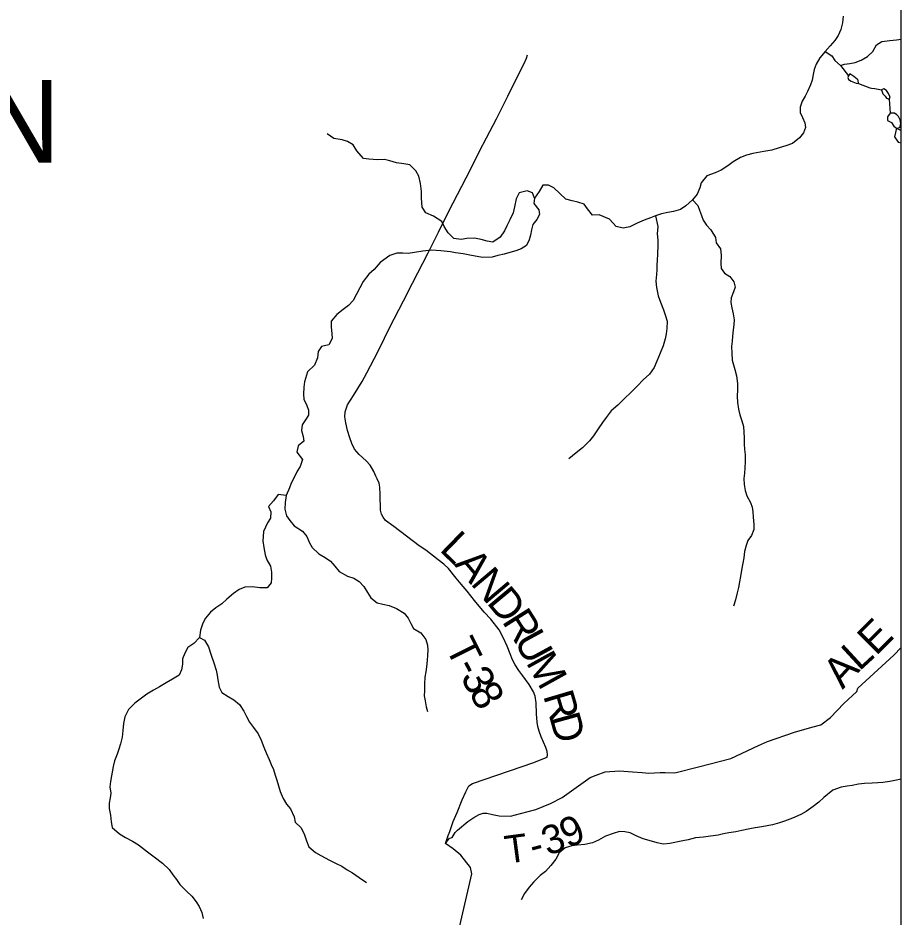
# Model space of a CAD drawing. Extents: x -139 to 835, y 0 to 440.
# Drawn here: x 550 to 607.6, y 239.4 to 298.1 of the extents above; entities that cross this region are included whole.
import ezdxf

# ---------------------------------------------------------------- set-up
doc = ezdxf.new("R2010")
doc.units = 0
for name, color, linetype in [('Default', 7, 'Continuous'), ('GM_X_Minor_Lake', 7, 'Continuous'), ('GM_X_Minor_River', 7, 'Continuous'), ('GM_X_Township_Road', 7, 'Continuous'), ('GM_X_Township_Road_Text', 7, 'Continuous'), ('GM_X_Township_Text', 7, 'Continuous'), ('SH_Cut_Line', 7, 'Continuous')]:
    doc.layers.add(name, color=color, linetype=linetype)

msp = doc.modelspace()

# ---------------------------------------------------------------- linework, layer by layer
at = {"layer": 'Default'}
msp.add_lwpolyline([(533.705, 218.461), (553.865, 217.083), (607.596, 213.413), (607.596, 313.688), (599.523, 343.435), (599.103, 345.232), (598.348, 346.669), (593.771, 354.537), (573.292, 389.29), (556.01, 382.105), (544.238, 377.806)], dxfattribs=at)
at = {"layer": 'GM_X_Minor_Lake'}
for points in [[(604.811, 294.022), (604.733, 294.095), (604.527, 294.265), (604.268, 294.424), (604.163, 294.305), (604.135, 294.186), (604.173, 294.065), (604.354, 293.955), (604.665, 293.82), (604.821, 293.794)], [(604.821, 293.794), (604.811, 294.022)], [(606.894, 292.884), (606.869, 292.957), (606.78, 293.15), (606.653, 293.343), (606.471, 293.453), (606.314, 293.395), (606.402, 293.118), (606.57, 292.984), (606.646, 292.839), (606.815, 292.777)], [(606.815, 292.777), (606.894, 292.884)], [(606.881, 291.877), (606.709, 291.639), (606.719, 291.387), (606.978, 291.264), (607.118, 291.023), (607.299, 290.889), (607.521, 290.922), (607.576, 291.162), (607.54, 291.426), (607.426, 291.643), (607.323, 291.764), (607.168, 291.862)], [(607.168, 291.862), (606.881, 291.877)]]:
    msp.add_lwpolyline(points, dxfattribs=at)
at = {"layer": 'GM_X_Minor_River'}
msp.add_line((607.299, 290.889), (607.596, 290.733), dxfattribs=at)
for points in [[(603.834, 298.184), (603.777, 297.764), (603.667, 297.322), (603.506, 296.928), (603.293, 296.606), (602.976, 296.262), (602.658, 295.893), (602.314, 295.465), (602.074, 295.072), (601.939, 294.713), (601.87, 294.39), (601.8, 294.019), (601.705, 293.708), (601.504, 293.278), (601.344, 292.968), (601.157, 292.658), (601.022, 292.264), (601.03, 291.904), (601.17, 291.59), (601.334, 291.241), (601.37, 290.928), (601.235, 290.594), (600.97, 290.249), (600.522, 289.894), (600.09, 289.731), (599.658, 289.603), (599.174, 289.452), (598.652, 289.362), (597.947, 289.238), (597.515, 289.134), (597.135, 288.983), (596.662, 288.688), (596.307, 288.428), (595.874, 288.156), (595.48, 287.969), (594.943, 287.77), (594.573, 287.319), (594.491, 287.008), (594.303, 286.59), (593.998, 286.221), (593.563, 285.818), (593.221, 285.594), (592.763, 285.455), (592.398, 285.399), (591.979, 285.295), (591.6, 285.167), (591.273, 285.051), (590.866, 284.887), (590.395, 284.688), (589.923, 284.466), (589.491, 284.374), (589.024, 284.475), (588.587, 284.948), (587.926, 285.231), (587.482, 285.212), (587.162, 285.623), (586.944, 285.925), (586.529, 286.074), (586.165, 286.15), (585.749, 286.262), (584.964, 287.002), (584.614, 287.162), (584.262, 287.166), (584.009, 286.749), (583.717, 286.32), (583.674, 285.973), (583.994, 285.561), (584.029, 285.249), (583.869, 284.939), (583.591, 284.606), (583.508, 284.259), (583.439, 283.912), (583.37, 283.601), (583.195, 283.231), (582.841, 283.031), (582.487, 282.89), (582.108, 282.787), (581.742, 282.682), (581.31, 282.579), (580.944, 282.475), (580.318, 282.446), (579.486, 282.599), (579.057, 282.688), (578.563, 282.765), (578.225, 282.816), (577.6, 282.895), (576.988, 282.926), (576.427, 282.86), (575.892, 282.782), (575.474, 282.714)], [(603.663, 294.983), (603.912, 295.052), (604.251, 295.108), (604.617, 295.176), (604.997, 295.328), (605.417, 295.563), (605.76, 295.884), (606, 296.313), (606.342, 296.549), (606.877, 296.604), (607.308, 296.659), (607.596, 296.702)], [(602.658, 295.893), (603.098, 295.612), (603.289, 295.31), (603.663, 294.983), (604.163, 294.305)], [(604.821, 293.794), (605.571, 293.525), (605.668, 293.49), (605.899, 293.472), (606.314, 293.395)], [(606.815, 292.777), (606.881, 291.877)], [(607.299, 290.889), (607.174, 290.326), (607.404, 289.976), (607.596, 289.933)], [(583.717, 286.32), (583.578, 286.681), (583.228, 286.805), (582.718, 286.667), (582.518, 286.285), (582.407, 285.77), (582.31, 285.364), (582.109, 284.922), (581.909, 284.516), (581.748, 284.194), (581.469, 283.777), (580.996, 283.446), (580.632, 283.51), (580.229, 283.623), (579.787, 283.711), (579.305, 283.693), (578.939, 283.625), (578.457, 283.69), (578.071, 284.066), (577.829, 284.476), (577.664, 284.802), (577.134, 285.156), (576.615, 285.365), (576.385, 285.728), (576.363, 286.028), (576.341, 286.34), (576.333, 286.76), (576.288, 287.276), (576.177, 287.769), (575.973, 288.107), (575.587, 288.495), (575.184, 288.572), (574.716, 288.637), (574.274, 288.761), (573.936, 288.849), (573.48, 288.83), (572.92, 288.86), (572.569, 288.912), (572.119, 289.409), (571.889, 289.795), (571.514, 290.027), (571.177, 290.127), (570.631, 290.217), (570.204, 290.509)], [(593.998, 286.221), (594.358, 285.857), (594.459, 285.544), (594.585, 285.195), (594.711, 284.882), (594.915, 284.568), (595.198, 284.253), (595.504, 283.758), (595.552, 283.421), (595.834, 283.022), (595.881, 282.614), (595.848, 282.063), (595.87, 281.738), (596.1, 281.436), (596.436, 281.216), (596.706, 280.866), (596.792, 280.529), (596.684, 280.206), (596.523, 279.836), (596.506, 279.512), (596.566, 279.164), (596.653, 278.779), (596.713, 278.382), (596.709, 278.071), (596.665, 277.735), (596.608, 277.316), (596.591, 277.004), (596.547, 276.657), (596.568, 276.225), (596.601, 275.757), (596.675, 275.456), (596.763, 275.143), (596.875, 274.734), (596.947, 274.241), (596.941, 273.833), (596.91, 273.414), (596.931, 272.994), (597.003, 272.573), (597.09, 272.2), (597.228, 271.815), (597.328, 271.442), (597.362, 271.07), (597.37, 270.686), (597.378, 270.29), (597.4, 269.942), (597.434, 269.582), (597.442, 269.126), (597.423, 268.73), (597.393, 268.395), (597.362, 268.035), (597.384, 267.663), (597.431, 267.267), (597.543, 266.905), (597.786, 266.483), (597.886, 266.17), (597.934, 265.87), (597.956, 265.522), (598.002, 265.053), (598.011, 264.717), (597.862, 264.323), (597.611, 264.002), (597.502, 263.667), (597.406, 263.284), (597.349, 262.877), (597.292, 262.518), (597.208, 262.075), (597.125, 261.656), (597.068, 261.309), (596.998, 260.926), (596.928, 260.578), (596.805, 260.124), (596.683, 259.729)], [(591.6, 285.167), (591.747, 284.482), (591.702, 284.003), (591.736, 283.582), (591.745, 283.258), (591.724, 282.683), (591.706, 282.287), (591.689, 281.963), (591.672, 281.652), (591.655, 281.352), (591.623, 280.908), (591.657, 280.5), (591.768, 279.947), (591.919, 279.538), (592.108, 279.032), (592.234, 278.719), (592.346, 278.297), (592.34, 277.818), (592.296, 277.482), (592.227, 277.147), (592.091, 276.693), (591.902, 276.227), (591.687, 275.701), (591.512, 275.283), (591.194, 274.843), (590.798, 274.475), (590.415, 274.084), (589.98, 273.656), (589.571, 273.265), (589.135, 272.826), (588.713, 272.447), (588.369, 272.03), (588.13, 271.697), (587.864, 271.28), (587.546, 270.828), (587.294, 270.507), (586.832, 270.044), (586.424, 269.712), (585.95, 269.333)], [(575.474, 282.714), (575.135, 282.73), (574.744, 282.734), (574.286, 282.583), (573.655, 282.122), (573.258, 281.683), (572.902, 281.362), (572.544, 280.887), (572.317, 280.481), (572.117, 280.063), (571.89, 279.646), (571.586, 279.325), (571.231, 279.065), (570.823, 278.746), (570.452, 278.306), (570.447, 277.922), (570.507, 277.502), (570.529, 277.177), (570.302, 276.76), (569.831, 276.645), (569.619, 276.336), (569.574, 275.904), (569.36, 275.427), (568.924, 275), (568.72, 274.354), (568.677, 273.995), (568.645, 273.551), (568.68, 273.227), (568.87, 272.805), (568.97, 272.504), (568.979, 272.18), (568.78, 271.87), (568.567, 271.537), (568.523, 271.177), (568.636, 270.792), (568.671, 270.48), (568.315, 270.172), (568.218, 269.753), (568.577, 269.281), (568.428, 268.827), (568.229, 268.517), (568.014, 268.064), (567.854, 267.742), (567.732, 267.431), (567.518, 266.941), (567.447, 266.486), (567.441, 266.043), (567.553, 265.609), (567.757, 265.295), (568.04, 264.968), (568.583, 264.615), (568.865, 264.264), (569.042, 263.854), (569.208, 263.552), (569.659, 263.14), (570.059, 262.883), (570.421, 262.651), (570.704, 262.337), (570.986, 261.986), (571.53, 261.68), (571.932, 261.543), (572.281, 261.336), (572.59, 261.009), (572.819, 260.61), (573.036, 260.272), (573.462, 259.944), (573.826, 259.844), (574.229, 259.767), (574.721, 259.57), (575.213, 259.265), (575.482, 258.938), (575.647, 258.588), (575.826, 258.263), (576.291, 257.97), (576.624, 257.546), (576.724, 257.173), (576.759, 256.849), (576.729, 256.514), (576.711, 256.166), (576.667, 255.771), (576.624, 255.447), (576.567, 255.088), (576.548, 254.644), (576.53, 254.225), (576.525, 253.877), (576.573, 253.552), (576.647, 253.156), (576.734, 252.843)], [(567.518, 266.941), (567.01, 266.995), (566.692, 266.578), (566.375, 266.222), (566.527, 265.872), (566.508, 265.453), (566.309, 265.143), (566.054, 264.594), (566.024, 264.27), (566.007, 263.971), (566.067, 263.538), (566.165, 263.057), (566.265, 262.732), (566.507, 262.334), (566.568, 261.937), (566.562, 261.542), (566.546, 261.242), (566.281, 260.909), (565.799, 260.914), (565.33, 260.979), (564.822, 260.949), (564.455, 260.809), (564.1, 260.549), (563.652, 260.17), (563.322, 259.861), (562.941, 259.601), (562.585, 259.329), (562.268, 258.937), (562.081, 258.615), (561.945, 258.149), (561.874, 257.67), (561.504, 257.29), (561.122, 257.018), (560.909, 256.649), (560.774, 256.29), (560.757, 255.93), (560.7, 255.571), (560.552, 255.225), (560.106, 254.954), (559.699, 254.718), (559.265, 254.459), (558.884, 254.235), (558.451, 253.988), (558.004, 253.657), (557.649, 253.385), (557.252, 252.97), (556.999, 252.492), (556.915, 252.062), (556.883, 251.618), (556.825, 251.175), (556.729, 250.732), (556.607, 250.386), (556.499, 250.063), (556.337, 249.633), (556.241, 249.274), (556.072, 248.292), (556.028, 247.933), (556.088, 247.524), (556.045, 247.213), (555.976, 246.878), (555.984, 246.53), (556.083, 246.097), (556.117, 245.665), (556.19, 245.28), (556.667, 244.867), (557.055, 244.635), (557.508, 244.402), (557.909, 244.146), (558.49, 243.708), (558.929, 243.379), (559.471, 242.954), (559.908, 242.541), (560.126, 242.203), (560.369, 241.888), (560.6, 241.574), (561.037, 241.138), (561.372, 240.798), (561.667, 240.447), (561.859, 240.133), (562.036, 239.735), (562.109, 239.351)], [(561.874, 257.67), (562.197, 257.498), (562.465, 257.076), (562.641, 256.534), (562.817, 256.028), (562.954, 255.535), (563.028, 255.222), (563.076, 254.91), (563.149, 254.429), (563.34, 254.091), (563.753, 253.823), (564.115, 253.615), (564.476, 253.311), (564.757, 252.864), (564.936, 252.527), (565.127, 252.165), (565.396, 251.814), (565.703, 251.403), (565.893, 250.981), (566.07, 250.535), (566.209, 250.15), (566.412, 249.728), (566.551, 249.39), (566.69, 249.077), (566.815, 248.692), (566.916, 248.367), (567.028, 248.006), (567.141, 247.633), (567.331, 247.187), (567.547, 246.813), (567.804, 246.498), (568.045, 245.992), (568.119, 245.643), (568.505, 245.255), (568.721, 244.797), (568.846, 244.424), (569.011, 244.026), (569.436, 243.662), (569.772, 243.466), (570.355, 243.148), (570.782, 242.939), (571.158, 242.755), (571.494, 242.536), (571.843, 242.34), (572.282, 242.024), (572.76, 241.707)], [(607.596, 248.431), (607.198, 248.353), (606.871, 248.296), (606.414, 248.229), (606.075, 248.209), (605.71, 248.177), (605.214, 248.146), (604.823, 248.115), (604.405, 248.035), (604.079, 247.979), (603.7, 247.911), (603.163, 247.725), (602.571, 247.251), (602.241, 246.931), (601.872, 246.659), (601.412, 246.328), (601.057, 246.128), (600.52, 245.894), (600.009, 245.695), (599.682, 245.591), (599.225, 245.464), (598.872, 245.384), (598.532, 245.339), (598.101, 245.26), (597.749, 245.204), (597.226, 245.09), (596.821, 245.01), (596.377, 244.943), (596.037, 244.874), (595.684, 244.794), (595.188, 244.716), (594.718, 244.661), (594.196, 244.606), (593.713, 244.492), (593.373, 244.411), (592.523, 244.24), (592.119, 244.197), (591.703, 244.285), (591.326, 244.397), (590.794, 244.547), (590.327, 244.744), (589.939, 244.928), (589.601, 245.004), (589.249, 245.019), (588.831, 244.892), (588.346, 244.717), (587.874, 244.458), (587.494, 244.295), (586.997, 244.18), (586.488, 244.126), (586.136, 244.081), (585.704, 243.954), (585.322, 243.634), (585.108, 243.217), (584.777, 242.813), (584.42, 242.421), (584.078, 242.148), (583.656, 241.745), (583.352, 241.401), (583.046, 240.972), (582.846, 240.578)]]:
    msp.add_lwpolyline(points, dxfattribs=at)
at = {"layer": 'GM_X_Township_Road'}
for points in [[(584.543, 249.862), (584.553, 250.024), (584.538, 250.234), (584.449, 250.492), (584.294, 250.845), (584.139, 251.197), (584.013, 251.557), (583.925, 251.869), (583.873, 252.16), (583.843, 252.696), (583.814, 253.415), (583.747, 253.855), (583.651, 254.133), (583.37, 254.601), (582.949, 255.178), (582.698, 255.517), (582.446, 255.903), (582.276, 256.215), (582.121, 256.609), (581.936, 257.11), (581.693, 257.632), (581.412, 258.175), (580.857, 258.867), (580.429, 259.334), (579.808, 260.094), (579.312, 260.691), (578.921, 261.152), (578.603, 261.552), (578.093, 262.176), (577.805, 262.447), (577.428, 262.739), (576.622, 263.369), (576.193, 263.654), (574.53, 264.908), (574.006, 265.315), (573.843, 265.512), (573.747, 265.709), (573.68, 265.98), (573.643, 267.011), (573.636, 267.478), (573.577, 267.75), (573.459, 268.014), (573.362, 268.204), (573.229, 268.509), (572.993, 268.916), (572.733, 269.201), (572.276, 269.608), (571.973, 269.967), (571.795, 270.32), (571.67, 270.699), (571.529, 271.174), (571.404, 271.669), (571.352, 272.056), (571.367, 272.395), (571.515, 272.849), (571.914, 273.466), (572.475, 274.361), (572.779, 274.944), (573.488, 276.301), (573.932, 277.189), (574.257, 277.86), (575.173, 279.63), (575.765, 280.776), (576.77, 282.756), (577.457, 284.099), (578.122, 285.475), (579.534, 288.188), (580.118, 289.388), (580.576, 290.256), (581.227, 291.504), (581.967, 292.968), (582.854, 294.78), (583.035, 295.099), (583.178, 295.443), (583.248, 295.675)], [(604.436, 253.888), (604.691, 254.124), (604.715, 254.146), (604.783, 254.363), (607.138, 256.525), (607.596, 257.032)], [(592.037, 248.869), (592.234, 248.864), (592.858, 248.847), (594.398, 249.232), (596.511, 249.792), (598.314, 250.638), (598.889, 250.903), (600.664, 251.51), (601.794, 251.831), (602.369, 251.978), (603.008, 252.468), (603.878, 253.373), (604.436, 253.888)], [(577.9, 244.243), (578.082, 244.764), (578.181, 245.034), (578.398, 245.669), (578.667, 246.27), (579.003, 247.093), (579.227, 247.62), (579.437, 248.005), (579.661, 248.159), (583.666, 249.534), (584.254, 249.753), (584.543, 249.862)], [(578.703, 238.314), (579.633, 242.274), (579.535, 242.672), (578.908, 243.479), (578.405, 243.896), (577.9, 244.243), (578.159, 244.584), (578.335, 244.629), (578.538, 244.963), (578.684, 245.104), (579.357, 245.676), (579.756, 245.946), (580.099, 246.139), (580.358, 246.222), (580.61, 246.216), (580.974, 246.139), (581.401, 246.036), (582.14, 246.026), (582.798, 246.193), (583.792, 246.463), (584.758, 246.849), (585.514, 247.234), (587.341, 248.538), (587.733, 248.693), (588.321, 248.924), (589.245, 248.975), (590.086, 248.924), (590.717, 248.863)], [(590.717, 248.863), (591.15, 248.821), (591.906, 248.872), (592.037, 248.869)]]:
    msp.add_lwpolyline(points, dxfattribs=at)
at = {"layer": 'SH_Cut_Line'}
msp.add_lwpolyline([(607.596, 213.413), (607.596, 400.079), (373.24, 400.079), (373.24, 228.621), (390.412, 227.867), (402.968, 227.036), (407.389, 226.858), (433.728, 225.419), (479.461, 222.215), (494.743, 221.147), (512.652, 220.106), (533.705, 218.461), (553.865, 217.083)], close=True, dxfattribs=at)

# ---------------------------------------------------------------- texts
at = {"layer": 'GM_X_Township_Road_Text'}
for s, height, rotation, p in [('L', 1.979, 315.92696, (577.454, 263.37)), ('A', 1.985, 310.49015, (578.43, 262.429)), ('N', 1.985, 310.14906, (579.49, 261.186)), ('D', 1.985, 309.74037, (580.543, 259.939)), ('R', 1.984, 302.29069, (581.552, 258.732)), ('E', 1.98, 45.00587, (605.965, 256.444)), ('U', 1.981, 298.62818, (582.343, 257.481)), ('T', 1.979, 296.61351, (577.864, 257.046)), ('M', 1.981, 298.99038, (583.121, 256.057)), ('L', 1.976, 42.62768, (604.87, 255.434)), ('A', 1.983, 47.53051, (603.791, 254.253)), ('3', 1.981, 298.4118, (578.849, 255.107)), ('-', 1.98, 297.48213, (578.489, 255.8)), ('8', 1.982, 299.30938, (579.4, 254.089)), ('R', 1.968, 286.47945, (584.258, 253.891)), ('D', 1.967, 285.56401, (584.677, 252.474)), ('9', 1.905, 24.67151, (585.889, 243.905)), ('3', 1.872, 19.21419, (584.564, 243.432)), ('T', 1.811, 7.57545, (581.891, 242.925)), ('-', 1.847, 15.03281, (583.634, 243.176))]:
    msp.add_text(s, height=height, rotation=rotation, dxfattribs=at).set_placement(p)
at = {"layer": 'GM_X_Township_Text'}
msp.add_text('PAXTON', height=5.3895, rotation=0.00001, dxfattribs=at).set_placement((523.171, 288.63))

doc.saveas('drawing.dxf')
